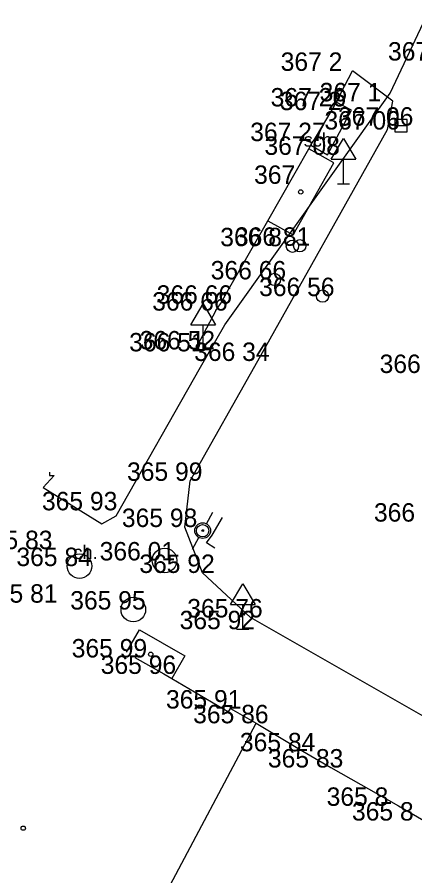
# Model space of a CAD drawing. Extents: x -688316 to -688024, y -973785 to -973591.
# Drawn here: x -688191.59 to -688175.42, y -973674.55 to -973639.59 of the extents above; entities that cross this region are included whole.
import ezdxf

# ---------------------------------------------------------------- set-up
doc = ezdxf.new("R2010")
doc.units = 0
for name, color, linetype in [('Vrstva 10', 7, 'Continuous'), ('Vrstva 11', 7, 'Continuous'), ('Vrstva 1_elektro CEZ', 7, 'Continuous'), ('Vrstva 27', 7, 'Continuous'), ('Vrstva 28_Verejne osvetleni', 7, 'Continuous'), ('Vrstva 3', 7, 'Continuous'), ('Vrstva 31', 7, 'Continuous'), ('Vrstva 34', 7, 'Continuous'), ('Vrstva 40', 7, 'Continuous'), ('Vrstva 41', 7, 'Continuous'), ('Vrstva 5', 7, 'Continuous'), ('Vrstva 58', 7, 'Continuous'), ('Vrstva 6', 7, 'Continuous')]:
    doc.layers.add(name, color=color, linetype=linetype)

# ---------------------------------------------------------------- blocks, each defined once
blk = doc.blocks.new('DZ')
at = {"layer": 'Vrstva 34'}
for p, q in [((-5, 10), (0, 18.5)), ((0, 18.5), (5, 10)), ((-5, 10), (5, 10)), ((0, 0), (0, 10)), ((-2.49, 0), (2.49, 0))]:
    blk.add_line(p, q, dxfattribs=at)
blk = doc.blocks.new('B_NESP')
at = {"layer": 'Vrstva 58'}
blk.add_circle((0, 0), 0.875, dxfattribs=at)
blk = doc.blocks.new('SV')
at = {"layer": 'Vrstva 28_Verejne osvetleni'}
blk.add_circle((0, 0), 2.5, dxfattribs=at)
blk = doc.blocks.new('SP')
at = {"layer": 'Vrstva 31'}
blk.add_circle((0, 0), 2.5, dxfattribs=at)
blk = doc.blocks.new('SKSCH0')
at = {"layer": 'Vrstva 41'}
blk.add_text('sch.', height=5.5, dxfattribs=at).set_placement((-8.15, -3.04))
blk = doc.blocks.new('VP')
at = {"layer": 'Vrstva 27'}
blk.add_line((-2.5, 0), (2.5, 0), dxfattribs=at)
blk.add_lwpolyline([(-2.5, -2.5), (2.5, -2.5), (2.5, 2.5), (-2.5, 2.5)], close=True, dxfattribs=at)
blk = doc.blocks.new('SAK')
at = {"layer": 'Vrstva 27'}
blk.add_circle((0, 0), 5, dxfattribs=at)
blk = doc.blocks.new('DKCH0')
at = {"layer": 'Vrstva 40'}
blk.add_text('ch.', height=5.5, dxfattribs=at).set_placement((-6.26, -3.04))
blk = doc.blocks.new('SOU_30')
at = {"layer": 'Vrstva 11'}
for p, q in [((4.95, 0), (13.26, -0.01)), ((-13.25, -0.01), (-4.95, 0))]:
    blk.add_line(p, q, dxfattribs=at)
for radius in [4.94, 0.584]:
    blk.add_circle((0, 0), radius, dxfattribs=at)

msp = doc.modelspace()

# ---------------------------------------------------------------- linework, layer by layer
at = {"layer": 'Vrstva 10'}
for p, q in [((-688181.8, -973653.59), (-688176.53, -973644.17)), ((-688184.56, -973658.47), (-688181.8, -973653.59)), ((-688164.44, -973674.16), (-688182.11, -973664.03))]:
    msp.add_line(p, q, dxfattribs=at)
for points in [[(-688176.53, -973644.17), (-688176.32, -973643.02), (-688177.96, -973641.78)], [(-688182.11, -973664.03), (-688184.06, -973662.22), (-688184.77, -973660.35), (-688184.56, -973658.47)]]:
    msp.add_lwpolyline(points, dxfattribs=at)
at = {"layer": 'Vrstva 11'}
msp.add_lwpolyline([(-688179.65, -973644.81), (-688178.97, -973645.2), (-688177.99, -973643.38), (-688178.62, -973643.05)], dxfattribs=at)
at = {"layer": 'Vrstva 1_elektro CEZ'}
msp.add_lwpolyline([(-688190.282, -973658.121), (-688190.282, -973658.255), (-688190.094, -973658.256), (-688190.531, -973658.736), (-688188.15, -973660.224), (-688187.569, -973659.901), (-688184.139, -973653.841), (-688183.153, -973652.126), (-688176.422, -973642.693), (-688173.607, -973636.693), (-688162.702, -973616.499), (-688163.01, -973615.648), (-688168.054, -973613.093), (-688168.316, -973613.534), (-688168.345, -973613.555), (-688168.465, -973613.555), (-688168.465, -973613.42)], dxfattribs=at)
at = {"layer": 'Vrstva 5'}
for p, q in [((-688194.65, -973692.33), (-688181.87, -973668.34)), ((-688181.87, -973668.34), (-688179.97, -973669.48)), ((-688178.83, -973670.14), (-688176.09, -973671.7))]:
    msp.add_line(p, q, dxfattribs=at)
for points in [[(-688178.72, -973643.23), (-688178.62, -973643.05), (-688177.96, -973641.78)], [(-688183.51, -973651.54), (-688183.33, -973651.26), (-688183, -973650.68), (-688181.4, -973647.88), (-688179.73, -973644.96), (-688179.65, -973644.81), (-688179.55, -973644.64)], [(-688181.4, -973647.88), (-688180.37, -973648.46), (-688178.72, -973645.53), (-688179.73, -973644.96)], [(-688183.67, -973660.68), (-688183.24, -973659.96)], [(-688183.554, -973661.216), (-688183.889, -973660.997), (-688183.67, -973660.68)], [(-688187.15, -973665.45), (-688186.62, -973664.53), (-688184.77, -973665.59), (-688185.3, -973666.52)], [(-688185.63, -973666.33), (-688185.3, -973666.52), (-688183, -973667.88), (-688182.92, -973667.74), (-688181.87, -973668.34)]]:
    msp.add_lwpolyline(points, dxfattribs=at)
at = {"layer": 'Vrstva 6'}
for p, q in [((-688178.72, -973643.23), (-688179.55, -973644.64)), ((-688183.51, -973651.54), (-688184.4, -973653.2)), ((-688186.81, -973665.66), (-688185.63, -973666.33)), ((-688179.97, -973669.48), (-688178.83, -973670.14)), ((-688176.09, -973671.7), (-688175.06, -973672.3))]:
    msp.add_line(p, q, dxfattribs=at)

# ---------------------------------------------------------------- block references
at = {"layer": 'Vrstva 11', "xscale": 0.06459975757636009, "yscale": 0.06459975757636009, "rotation": 61.133095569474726}
msp.add_blockref('SOU_30', (-688184.049, -973660.498), dxfattribs=at)
at = {"layer": 'Vrstva 27', "xscale": 0.1, "yscale": 0.10000000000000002}
for name, p in [('VP', (-688175.98, -973644.01)), ('SAK', (-688185.6, -973661.71)), ('SAK', (-688189.06, -973661.94)), ('SAK', (-688186.87, -973663.71))]:
    msp.add_blockref(name, p, dxfattribs=at)
at = {"layer": 'Vrstva 28_Verejne osvetleni', "xscale": 0.1, "yscale": 0.10000000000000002}
for p in [(-688179.17, -973650.95), (-688184.05, -973660.5)]:
    msp.add_blockref('SV', p, dxfattribs=at)
at = {"layer": 'Vrstva 31', "xscale": 0.1, "yscale": 0.10000000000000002}
for p in [(-688180.4, -973648.92), (-688180.1, -973648.9), (-688181.13, -973650.27)]:
    msp.add_blockref('SP', p, dxfattribs=at)
at = {"layer": 'Vrstva 34', "xscale": 0.1, "yscale": 0.10000000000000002}
for p in [(-688178.32, -973646.38), (-688178.32, -973646.38), (-688178.32, -973646.38), (-688178.32, -973646.38), (-688184.03, -973653.12), (-688184.03, -973653.12), (-688184.03, -973653.12), (-688184.03, -973653.12), (-688182.42, -973664.51), (-688182.42, -973664.51), (-688182.42, -973664.51), (-688182.42, -973664.51)]:
    msp.add_blockref('DZ', p, dxfattribs=at)
at = {"layer": 'Vrstva 40', "xscale": 0.1, "yscale": 0.10000000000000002}
msp.add_blockref('DKCH0', (-688188.68, -973661.35), dxfattribs=at)
at = {"layer": 'Vrstva 41', "xscale": 0.1, "yscale": 0.10000000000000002}
msp.add_blockref('SKSCH0', (-688179.12, -973644.56), dxfattribs=at)
at = {"layer": 'Vrstva 58', "xscale": 0.1, "yscale": 0.10000000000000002}
for p in [(-688180.06, -973646.71), (-688180.06, -973646.71), (-688180.06, -973646.71), (-688180.06, -973646.71), (-688186.16, -973665.53), (-688186.16, -973665.53), (-688186.16, -973665.53), (-688186.16, -973665.53), (-688191.35, -973672.61), (-688191.35, -973672.61), (-688191.35, -973672.61), (-688191.35, -973672.61)]:
    msp.add_blockref('B_NESP', p, dxfattribs=at)

# ---------------------------------------------------------------- texts
at = {"layer": 'Vrstva 3'}
for s, p in [('367 16 ', (-688176.511, -973641.36)), ('367 16 ', (-688176.511, -973641.36)), ('367 16 ', (-688176.511, -973641.36)), ('367 16 ', (-688176.511, -973641.36)), ('367 16 ', (-688176.511, -973641.36)), ('367 16 ', (-688176.511, -973641.36)), ('367 16 ', (-688176.511, -973641.36)), ('367 2  ', (-688180.877, -973641.78)), ('367 2  ', (-688180.877, -973641.78)), ('367 2  ', (-688180.877, -973641.78)), ('367 2  ', (-688180.877, -973641.78)), ('367 2  ', (-688180.877, -973641.78)), ('367 2  ', (-688180.877, -973641.78)), ('367 2  ', (-688180.877, -973641.78)), ('367 26 ', (-688181.286, -973643.23)), ('367 26 ', (-688181.286, -973643.23)), ('367 26 ', (-688181.286, -973643.23)), ('367 26 ', (-688181.286, -973643.23)), ('367 26 ', (-688181.286, -973643.23)), ('367 26 ', (-688181.286, -973643.23)), ('367 26 ', (-688181.286, -973643.23)), ('367 1  ', (-688179.293, -973643.02)), ('367 1  ', (-688179.293, -973643.02)), ('367 1  ', (-688179.293, -973643.02)), ('367 1  ', (-688179.293, -973643.02)), ('367 1  ', (-688179.293, -973643.02)), ('367 1  ', (-688179.293, -973643.02)), ('367 1  ', (-688179.293, -973643.02)), ('367 2  ', (-688180.907, -973643.38)), ('367 2  ', (-688180.907, -973643.38)), ('367 2  ', (-688180.907, -973643.38)), ('367 2  ', (-688180.907, -973643.38)), ('367 2  ', (-688180.907, -973643.38)), ('367 2  ', (-688180.907, -973643.38)), ('367 2  ', (-688180.907, -973643.38)), ('367 06 ', (-688179.096, -973644.17)), ('367 06 ', (-688179.096, -973644.17)), ('367 06 ', (-688179.096, -973644.17)), ('367 06 ', (-688179.096, -973644.17)), ('367 06 ', (-688179.096, -973644.17)), ('367 06 ', (-688179.096, -973644.17)), ('367 06 ', (-688179.096, -973644.17)), ('367 06 ', (-688178.546, -973644.01)), ('367 06 ', (-688178.546, -973644.01)), ('367 06 ', (-688178.546, -973644.01)), ('367 06 ', (-688178.546, -973644.01)), ('367 06 ', (-688178.546, -973644.01)), ('367 06 ', (-688178.546, -973644.01)), ('367 06 ', (-688178.546, -973644.01)), ('367 27 ', (-688182.116, -973644.64)), ('367 27 ', (-688182.116, -973644.64)), ('367 27 ', (-688182.116, -973644.64)), ('367 27 ', (-688182.116, -973644.64)), ('367 27 ', (-688182.116, -973644.64)), ('367 27 ', (-688182.116, -973644.64)), ('367 27 ', (-688182.116, -973644.64)), ('367 08 ', (-688181.536, -973645.2)), ('367 08 ', (-688181.536, -973645.2)), ('367 08 ', (-688181.536, -973645.2)), ('367 08 ', (-688181.536, -973645.2)), ('367 08 ', (-688181.536, -973645.2)), ('367 08 ', (-688181.536, -973645.2)), ('367 08 ', (-688181.536, -973645.2)), ('367    ', (-688181.957, -973646.38)), ('367    ', (-688181.957, -973646.38)), ('367    ', (-688181.957, -973646.38)), ('367    ', (-688181.957, -973646.38)), ('367    ', (-688181.957, -973646.38)), ('367    ', (-688181.957, -973646.38)), ('367    ', (-688181.957, -973646.38)), ('366 8  ', (-688183.335, -973648.92)), ('366 8  ', (-688183.335, -973648.92)), ('366 8  ', (-688183.335, -973648.92)), ('366 8  ', (-688183.335, -973648.92)), ('366 8  ', (-688183.335, -973648.92)), ('366 8  ', (-688183.335, -973648.92)), ('366 8  ', (-688183.335, -973648.92)), ('366 81 ', (-688182.739, -973648.9)), ('366 81 ', (-688182.739, -973648.9)), ('366 81 ', (-688182.739, -973648.9)), ('366 81 ', (-688182.739, -973648.9)), ('366 81 ', (-688182.739, -973648.9)), ('366 81 ', (-688182.739, -973648.9)), ('366 81 ', (-688182.739, -973648.9)), ('366 66 ', (-688183.722, -973650.27)), ('366 66 ', (-688183.722, -973650.27)), ('366 66 ', (-688183.722, -973650.27)), ('366 66 ', (-688183.722, -973650.27)), ('366 66 ', (-688183.722, -973650.27)), ('366 66 ', (-688183.722, -973650.27)), ('366 66 ', (-688183.722, -973650.27)), ('366 56 ', (-688181.753, -973650.95)), ('366 56 ', (-688181.753, -973650.95)), ('366 56 ', (-688181.753, -973650.95)), ('366 56 ', (-688181.753, -973650.95)), ('366 56 ', (-688181.753, -973650.95)), ('366 56 ', (-688181.753, -973650.95)), ('366 56 ', (-688181.753, -973650.95)), ('366 66 ', (-688185.922, -973651.26)), ('366 66 ', (-688185.922, -973651.26)), ('366 66 ', (-688185.922, -973651.26)), ('366 66 ', (-688185.922, -973651.26)), ('366 66 ', (-688185.922, -973651.26)), ('366 66 ', (-688185.922, -973651.26)), ('366 66 ', (-688185.922, -973651.26)), ('366 66 ', (-688186.102, -973651.54)), ('366 66 ', (-688186.102, -973651.54)), ('366 66 ', (-688186.102, -973651.54)), ('366 66 ', (-688186.102, -973651.54)), ('366 66 ', (-688186.102, -973651.54)), ('366 66 ', (-688186.102, -973651.54)), ('366 66 ', (-688186.102, -973651.54)), ('366 51 ', (-688187.039, -973653.2)), ('366 51 ', (-688187.039, -973653.2)), ('366 51 ', (-688187.039, -973653.2)), ('366 51 ', (-688187.039, -973653.2)), ('366 51 ', (-688187.039, -973653.2)), ('366 51 ', (-688187.039, -973653.2)), ('366 51 ', (-688187.039, -973653.2)), ('366 52 ', (-688186.613, -973653.12)), ('366 52 ', (-688186.613, -973653.12)), ('366 52 ', (-688186.613, -973653.12)), ('366 52 ', (-688186.613, -973653.12)), ('366 52 ', (-688186.613, -973653.12)), ('366 52 ', (-688186.613, -973653.12)), ('366 52 ', (-688186.613, -973653.12)), ('366 34 ', (-688184.395, -973653.59)), ('366 34 ', (-688184.395, -973653.59)), ('366 34 ', (-688184.395, -973653.59)), ('366 34 ', (-688184.395, -973653.59)), ('366 34 ', (-688184.395, -973653.59)), ('366 34 ', (-688184.395, -973653.59)), ('366 34 ', (-688184.395, -973653.59)), ('366 64 ', (-688176.852, -973654.08)), ('366 64 ', (-688176.852, -973654.08)), ('366 64 ', (-688176.852, -973654.08)), ('366 64 ', (-688176.852, -973654.08)), ('366 64 ', (-688176.852, -973654.08)), ('366 64 ', (-688176.852, -973654.08)), ('366 64 ', (-688176.852, -973654.08)), ('365 99 ', (-688187.126, -973658.47)), ('365 99 ', (-688187.126, -973658.47)), ('365 99 ', (-688187.126, -973658.47)), ('365 99 ', (-688187.126, -973658.47)), ('365 99 ', (-688187.126, -973658.47)), ('365 99 ', (-688187.126, -973658.47)), ('365 99 ', (-688187.126, -973658.47)), ('365 93 ', (-688190.586, -973659.67)), ('365 93 ', (-688190.586, -973659.67)), ('365 93 ', (-688190.586, -973659.67)), ('365 93 ', (-688190.586, -973659.67)), ('365 93 ', (-688190.586, -973659.67)), ('365 93 ', (-688190.586, -973659.67)), ('365 93 ', (-688190.586, -973659.67)), ('365 98 ', (-688187.336, -973660.35)), ('365 98 ', (-688187.336, -973660.35)), ('365 98 ', (-688187.336, -973660.35)), ('365 98 ', (-688187.336, -973660.35)), ('365 98 ', (-688187.336, -973660.35)), ('365 98 ', (-688187.336, -973660.35)), ('365 98 ', (-688187.336, -973660.35)), ('366 28 ', (-688177.083, -973660.13)), ('366 28 ', (-688177.083, -973660.13)), ('366 28 ', (-688177.083, -973660.13)), ('366 28 ', (-688177.083, -973660.13)), ('366 28 ', (-688177.083, -973660.13)), ('366 28 ', (-688177.083, -973660.13)), ('366 28 ', (-688177.083, -973660.13)), ('365 83 ', (-688193.226, -973661.25)), ('365 83 ', (-688193.226, -973661.25)), ('365 83 ', (-688193.226, -973661.25)), ('365 83 ', (-688193.226, -973661.25)), ('365 83 ', (-688193.226, -973661.25)), ('365 83 ', (-688193.226, -973661.25)), ('365 83 ', (-688193.226, -973661.25)), ('366 01 ', (-688188.239, -973661.71)), ('366 01 ', (-688188.239, -973661.71)), ('366 01 ', (-688188.239, -973661.71)), ('366 01 ', (-688188.239, -973661.71)), ('366 01 ', (-688188.239, -973661.71)), ('366 01 ', (-688188.239, -973661.71)), ('366 01 ', (-688188.239, -973661.71)), ('365 84 ', (-688191.626, -973661.94)), ('365 84 ', (-688191.626, -973661.94)), ('365 84 ', (-688191.626, -973661.94)), ('365 84 ', (-688191.626, -973661.94)), ('365 84 ', (-688191.626, -973661.94)), ('365 84 ', (-688191.626, -973661.94)), ('365 84 ', (-688191.626, -973661.94)), ('365 92 ', (-688186.626, -973662.22)), ('365 92 ', (-688186.626, -973662.22)), ('365 92 ', (-688186.626, -973662.22)), ('365 92 ', (-688186.626, -973662.22)), ('365 92 ', (-688186.626, -973662.22)), ('365 92 ', (-688186.626, -973662.22)), ('365 92 ', (-688186.626, -973662.22)), ('365 81 ', (-688193.021, -973663.43)), ('365 81 ', (-688193.021, -973663.43)), ('365 81 ', (-688193.021, -973663.43)), ('365 81 ', (-688193.021, -973663.43)), ('365 81 ', (-688193.021, -973663.43)), ('365 81 ', (-688193.021, -973663.43)), ('365 81 ', (-688193.021, -973663.43)), ('365 95 ', (-688189.436, -973663.71)), ('365 95 ', (-688189.436, -973663.71)), ('365 95 ', (-688189.436, -973663.71)), ('365 95 ', (-688189.436, -973663.71)), ('365 95 ', (-688189.436, -973663.71)), ('365 95 ', (-688189.436, -973663.71)), ('365 95 ', (-688189.436, -973663.71)), ('365 76 ', (-688184.676, -973664.03)), ('365 76 ', (-688184.676, -973664.03)), ('365 76 ', (-688184.676, -973664.03)), ('365 76 ', (-688184.676, -973664.03)), ('365 76 ', (-688184.676, -973664.03)), ('365 76 ', (-688184.676, -973664.03)), ('365 76 ', (-688184.676, -973664.03)), ('365 92 ', (-688184.986, -973664.51)), ('365 92 ', (-688184.986, -973664.51)), ('365 92 ', (-688184.986, -973664.51)), ('365 92 ', (-688184.986, -973664.51)), ('365 92 ', (-688184.986, -973664.51)), ('365 92 ', (-688184.986, -973664.51)), ('365 92 ', (-688184.986, -973664.51)), ('365 99 ', (-688189.376, -973665.66)), ('365 99 ', (-688189.376, -973665.66)), ('365 99 ', (-688189.376, -973665.66)), ('365 99 ', (-688189.376, -973665.66)), ('365 99 ', (-688189.376, -973665.66)), ('365 99 ', (-688189.376, -973665.66)), ('365 99 ', (-688189.376, -973665.66)), ('365 96 ', (-688188.196, -973666.33)), ('365 96 ', (-688188.196, -973666.33)), ('365 96 ', (-688188.196, -973666.33)), ('365 96 ', (-688188.196, -973666.33)), ('365 96 ', (-688188.196, -973666.33)), ('365 96 ', (-688188.196, -973666.33)), ('365 96 ', (-688188.196, -973666.33)), ('365 91 ', (-688185.541, -973667.74)), ('365 91 ', (-688185.541, -973667.74)), ('365 91 ', (-688185.541, -973667.74)), ('365 91 ', (-688185.541, -973667.74)), ('365 91 ', (-688185.541, -973667.74)), ('365 91 ', (-688185.541, -973667.74)), ('365 91 ', (-688185.541, -973667.74)), ('365 86 ', (-688184.436, -973668.34)), ('365 86 ', (-688184.436, -973668.34)), ('365 86 ', (-688184.436, -973668.34)), ('365 86 ', (-688184.436, -973668.34)), ('365 86 ', (-688184.436, -973668.34)), ('365 86 ', (-688184.436, -973668.34)), ('365 86 ', (-688184.436, -973668.34)), ('365 84 ', (-688182.536, -973669.48)), ('365 84 ', (-688182.536, -973669.48)), ('365 84 ', (-688182.536, -973669.48)), ('365 84 ', (-688182.536, -973669.48)), ('365 84 ', (-688182.536, -973669.48)), ('365 84 ', (-688182.536, -973669.48)), ('365 84 ', (-688182.536, -973669.48)), ('365 83 ', (-688181.396, -973670.14)), ('365 83 ', (-688181.396, -973670.14)), ('365 83 ', (-688181.396, -973670.14)), ('365 83 ', (-688181.396, -973670.14)), ('365 83 ', (-688181.396, -973670.14)), ('365 83 ', (-688181.396, -973670.14)), ('365 83 ', (-688181.396, -973670.14)), ('365 8  ', (-688179.007, -973671.7)), ('365 8  ', (-688179.007, -973671.7)), ('365 8  ', (-688179.007, -973671.7)), ('365 8  ', (-688179.007, -973671.7)), ('365 8  ', (-688179.007, -973671.7)), ('365 8  ', (-688179.007, -973671.7)), ('365 8  ', (-688179.007, -973671.7)), ('365 8  ', (-688177.977, -973672.3)), ('365 8  ', (-688177.977, -973672.3)), ('365 8  ', (-688177.977, -973672.3)), ('365 8  ', (-688177.977, -973672.3)), ('365 8  ', (-688177.977, -973672.3)), ('365 8  ', (-688177.977, -973672.3)), ('365 8  ', (-688177.977, -973672.3))]:
    msp.add_text(s, height=0.75, dxfattribs=at).set_placement(p)

doc.saveas('drawing.dxf')
